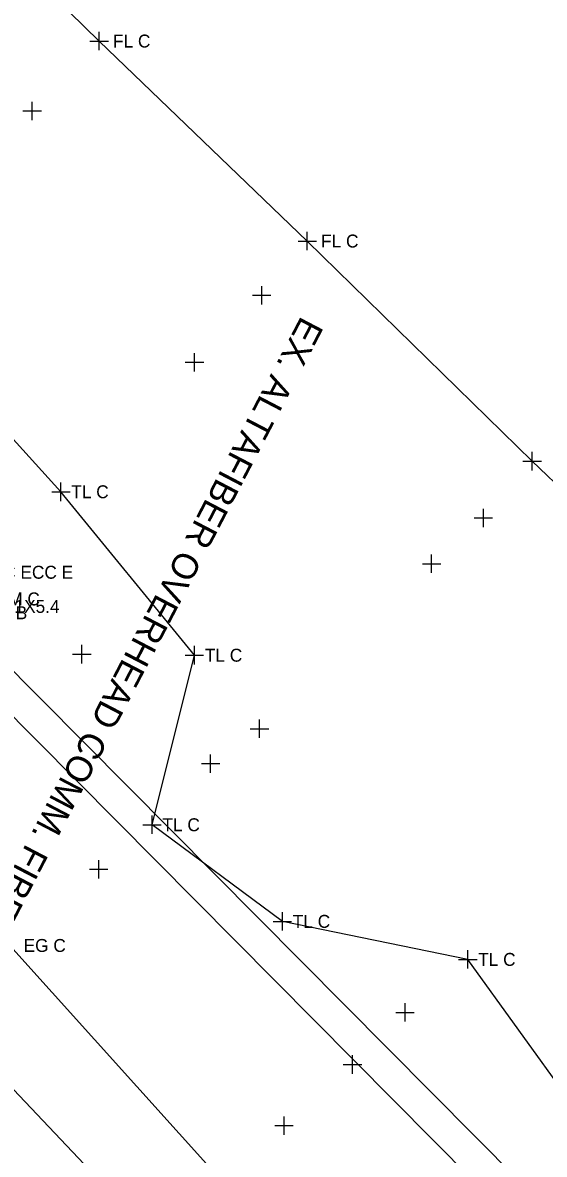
# Model space of a CAD drawing. Extents: x 1324236 to 1326110, y 459090 to 460782.
# Drawn here: x 1325803.8 to 1325860.4, y 459753.2 to 459875.9 of the extents above; entities that cross this region are included whole.
import ezdxf

# ---------------------------------------------------------------- set-up
doc = ezdxf.new("R2010")
doc.units = 0
for name, color, linetype in [('DV_X_Property_Line', 7, 'Continuous'), ('PM_X_CL_Double_Solid', 7, 'Continuous'), ('PM_X_Edge_Line', 7, 'Continuous'), ('PV_X_Shoulder', 7, 'Continuous'), ('PV_X_Shoulder_Aggregate', 7, 'Continuous'), ('RD_X_GR_Lt', 7, 'Continuous'), ('RW_X_CL', 7, 'Continuous'), ('RW_X_Esmt_SH', 7, 'Continuous'), ('UT_X_Telecom', 7, 'Continuous'), ('VG_X_Flower_Bed', 7, 'Continuous')]:
    doc.layers.add(name, color=color, linetype=linetype)

msp = doc.modelspace()

# ---------------------------------------------------------------- linework, layer by layer
at = {"layer": 'PM_X_CL_Double_Solid'}
for p, q in [((1325789.06, 459896.5), (1325812.12, 459873.88)), ((1325812.12, 459873.88), (1325834.68, 459852.21)), ((1325834.68, 459852.21), (1325859.06, 459828.36)), ((1325859.06, 459828.36), (1325883.59, 459804.73))]:
    msp.add_line(p, q, dxfattribs=at)
at = {"layer": 'PM_X_Edge_Line'}
msp.add_arc((1383694.65, 514882.33), 79942.57, 223.5885223, 223.6119585, dxfattribs=at)
at = {"layer": 'PV_X_Shoulder'}
msp.add_lwpolyline([(1325700.04, 459879.13), (1325707.06, 459870.28), (1325707.06, 459870.28), (1325727.09, 459845.4), (1325727.09, 459845.4), (1325727.91, 459844.4), (1325727.91, 459844.4), (1325739.84, 459830.12), (1325739.84, 459830.12), (1325749.18, 459819.36), (1325749.18, 459819.36), (1325758, 459809.46), (1325758, 459809.46), (1325771.86, 459794.03), (1325771.86, 459794.03), (1325787.36, 459776.87), (1325787.36, 459776.87), (1325794.6, 459768.92), (1325794.6, 459768.92), (1325795.1, 459768.39), (1325795.1, 459768.39), (1325818.19, 459744.06)], dxfattribs=at)
at = {"layer": 'PV_X_Shoulder_Aggregate'}
msp.add_lwpolyline([(1325606.5, 460003.97), (1325627.86, 459979.71), (1325648.47, 459953.75), (1325670.82, 459926.9), (1325690.92, 459900.29), (1325711.62, 459873.72), (1325733.33, 459849.01), (1325756.75, 459825.62), (1325779.78, 459800.49), (1325802.43, 459775.88), (1325825.37, 459750.4), (1325848.07, 459724.61), (1325869.88, 459700.51), (1325892.16, 459676.27), (1325913.97, 459651.72)], dxfattribs=at)
at = {"layer": 'RD_X_GR_Lt'}
for p, q in [((1325807.98, 459825.04), (1325792.8, 459841.69)), ((1325822.45, 459807.33), (1325807.98, 459825.04)), ((1325817.86, 459788.96), (1325822.45, 459807.33)), ((1325831.99, 459778.49), (1325817.86, 459788.96)), ((1325852.09, 459774.37), (1325831.99, 459778.49)), ((1325863.98, 459757.85), (1325852.09, 459774.37))]:
    msp.add_line(p, q, dxfattribs=at)
at = {"layer": 'RW_X_CL'}
for p, q in [((1325804.86, 459865.31), (1325804.86, 459867.31)), ((1325803.86, 459866.31), (1325805.86, 459866.31)), ((1325829.75, 459845.33), (1325829.75, 459847.33)), ((1325828.75, 459846.33), (1325830.75, 459846.33)), ((1325822.46, 459838.07), (1325822.46, 459840.07)), ((1325821.46, 459839.07), (1325823.46, 459839.07)), ((1325853.78, 459821.21), (1325853.78, 459823.21)), ((1325852.78, 459822.21), (1325854.78, 459822.21)), ((1325848.16, 459816.24), (1325848.16, 459818.24)), ((1325847.16, 459817.24), (1325849.16, 459817.24)), ((1325810.25, 459806.45), (1325810.25, 459808.45)), ((1325809.25, 459807.45), (1325811.25, 459807.45)), ((1325828.51, 459799.37), (1325830.51, 459799.37)), ((1325829.51, 459798.37), (1325829.51, 459800.37)), ((1325823.21, 459795.58), (1325825.21, 459795.58)), ((1325824.21, 459794.58), (1325824.21, 459796.58)), ((1325812.07, 459783.13), (1325812.07, 459785.13)), ((1325811.07, 459784.13), (1325813.07, 459784.13)), ((1325844.28, 459768.63), (1325846.28, 459768.63)), ((1325845.28, 459767.63), (1325845.28, 459769.63)), ((1325839.58, 459761.98), (1325839.58, 459763.98)), ((1325838.58, 459762.98), (1325840.58, 459762.98)), ((1325831.17, 459756.36), (1325833.17, 459756.36)), ((1325832.17, 459755.36), (1325832.17, 459757.36))]:
    msp.add_line(p, q, dxfattribs=at)
at = {"layer": 'RW_X_Esmt_SH'}
for p, q in [((1325812.12, 459872.88), (1325812.12, 459874.88)), ((1325811.12, 459873.88), (1325813.12, 459873.88)), ((1325834.68, 459851.21), (1325834.68, 459853.21)), ((1325833.68, 459852.21), (1325835.68, 459852.21)), ((1325859.06, 459827.36), (1325859.06, 459829.36)), ((1325858.06, 459828.36), (1325860.06, 459828.36)), ((1325806.98, 459825.04), (1325808.98, 459825.04)), ((1325807.98, 459824.04), (1325807.98, 459826.04)), ((1325822.45, 459806.33), (1325822.45, 459808.33)), ((1325821.45, 459807.33), (1325823.45, 459807.33)), ((1325817.86, 459787.96), (1325817.86, 459789.96)), ((1325816.86, 459788.96), (1325818.86, 459788.96)), ((1325830.99, 459778.49), (1325832.99, 459778.49)), ((1325831.99, 459777.49), (1325831.99, 459779.49)), ((1325852.09, 459773.37), (1325852.09, 459775.37)), ((1325851.09, 459774.37), (1325853.09, 459774.37))]:
    msp.add_line(p, q, dxfattribs=at)
at = {"layer": 'VG_X_Flower_Bed'}
for p, q in [((1325978.26, 459628.97), (1325795.75, 459812.7)), ((1325975.77, 459626.5), (1325793.27, 459810.24))]:
    msp.add_line(p, q, dxfattribs=at)

# ---------------------------------------------------------------- texts
at = {"layer": 'DV_X_Property_Line'}
for s, p in [('CSTM C ECC E', (1325795.89, 459815.62)), ('CSTM C', (1325798.52, 459812.73)), ('CSTM B ECC B', (1325791.01, 459811.23)), ('EG C', (1325803.93, 459775.18))]:
    msp.add_text(s, height=1.4, dxfattribs=at).set_placement(p)
at = {"layer": 'RW_X_CL'}
msp.add_text('CBGRT3.1X5.4', height=1.4, dxfattribs=at).set_placement((1325794.83, 459811.92))
at = {"layer": 'RW_X_Esmt_SH'}
for s, p in [('FL C', (1325813.62, 459873.18)), ('FL C', (1325836.18, 459851.51)), ('TL C', (1325809.1, 459824.34)), ('TL C', (1325823.58, 459806.63)), ('TL C', (1325818.98, 459788.26)), ('TL C', (1325833.11, 459777.79)), ('TL C', (1325853.21, 459773.67))]:
    msp.add_text(s, height=1.4, dxfattribs=at).set_placement(p)
at = {"layer": 'UT_X_Telecom'}
msp.add_text('EX. ALTAFIBER OVERHEAD COMM. FIBER', height=2.8, rotation=242.4449, dxfattribs=at).set_placement((1325834.04, 459844.18))

doc.saveas('drawing.dxf')
